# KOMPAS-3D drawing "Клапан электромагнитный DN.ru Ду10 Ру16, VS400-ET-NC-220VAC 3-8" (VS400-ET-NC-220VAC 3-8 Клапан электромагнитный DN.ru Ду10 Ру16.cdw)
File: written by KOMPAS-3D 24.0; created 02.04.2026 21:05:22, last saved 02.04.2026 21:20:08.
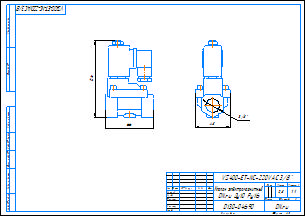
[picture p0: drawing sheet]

Document properties: c3d_UniqueCompID: ef56311e-7521-43dc-8291-0e6108b3d81d; Обозначение: VS400-ET-NC-220VAC 3-8; Наименование: Клапан электромагнитный DN.ru Ду10 Ру16; Автор: artio; Класс точности: c; Знак неуказанной шероховатости: Шероховатость не задана; Рассекать на разрезах: Да; Автор: artio; Форматы листов документа: A3; Полное имя файла: VS400-ET-NC-220VAC 3-8 Клапан электромагнитный DN.ru Ду10 Ру16.m3d; Масса: 0.797; Наименование: Клапан электромагнитный DN.ru Ду10 Ру16; Количество листов документа: 1; Примечание: D130-04690

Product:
- Body: Тело 1  | qty 1
    Масса: 1.030062
- Part/product: Клапан электромагнитный DN.ru Ду10 Ру16  | designation VS400-ET-NC-220VAC 3-8
    Масса: 0.797
    Раздел спецификации: Прочие изделия
    Примечание: D130-04690
    additional columns: ef56311e-7521-43dc-8291-0e6108b3d81d; VS400-ET-NC-220VAC 3-8; artio; c; Шероховатость не задана; Да

Views: Вид 1, Спереди, Проекционный вид 2
Referenced files in C:\Users\artio\OneDrive\Рабочий стол\Клапан электромагнитный DN.ru VS4x-xT-NC-x\DN10\: VS400-ET-NC-220VAC 3-8 Клапан электромагнитный DN.ru Ду10 Ру16.m3d
Referenced files in C:\Users\artio\OneDrive\Рабочий стол\Клапан электромагнитный DN.ru\VS400\VS400-ET-NC\VS400-ET-NC-220VAC\Ду10\: VS400-ET-NC-220VAC 3-8 Клапан электромагнитный DN.ru Ду10 Ру16.cdw, VS400-ET-NC-220VAC 3-8 Клапан электромагнитный DN.ru Ду10 Ру16.m3d
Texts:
  VS400-ET-NC-220VAC 3-8
  Линейный размер
  Клапан электромагнитный
  DN.ru Ду10 Ру16
  VS400-ET-NC-220VAC 3/8"
  VS400-ET-NC-220VAC 3/8"-
  Клапан электромагнитный DN.ru Ду10 Ру16
  VS400-ET-NC-220VAC 3-8 Клапан электромагнитный DN.ru Ду10 Ру16
Dimensions and other numbers on the sheet: 0; 3; 2; 4; 48; 3/8"; 66; 106; 1:1; 1; 0,8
